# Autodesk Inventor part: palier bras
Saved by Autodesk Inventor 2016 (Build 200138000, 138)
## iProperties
Created: 2013-10
Part Number: palier bras
Material: Générique
Document SubType Name: Modeling
Designer: Bruno
Density: 1 g/cm^3
Appearance: Par défaut
Author: Bruno
Sending System: SolidWorks 2013
Last Author: christophe
Last Saved: 2014-02-15
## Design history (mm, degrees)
feature "Chanfrein1"
node "Solide1"
